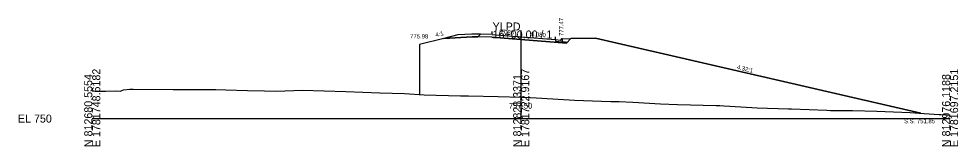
# Model space of a CAD drawing. Extents: x -26 to 353, y -10 to 9080.
# Drawn here: x -25.7 to 302.8, y 5990.3 to 6035 of the extents above; entities that cross this region are included whole.
import ezdxf

# ---------------------------------------------------------------- set-up
doc = ezdxf.new("R2010")
doc.units = 0
for name, color, linetype in [('Exist Cross Section Cell', 7, 'Continuous'), ('Exist XS Center Line Elevation Label', 7, 'Continuous'), ('Exist XS Ground Line', 7, 'Continuous'), ('Prop XS Ditch Slope Text', 7, 'Continuous'), ('Prop XS Dump Level', 7, 'Continuous'), ('Prop XS Earthwork Shape', 7, 'Continuous'), ('Prop XS EOT Tick Mark', 7, 'Continuous'), ('Prop XS Finish Grade', 7, 'Continuous'), ('Prop XS Finish Grade CurbGutter', 7, 'Continuous'), ('Prop XS Finish Grade Earthwork', 7, 'Continuous'), ('Prop XS Finish Grade Paved Shoulder', 7, 'Continuous'), ('Prop XS Finish Grade Pavement', 7, 'Continuous'), ('Prop XS Hydro Elevations', 7, 'Continuous'), ('Prop XS Pvmt Edge Slope', 7, 'Continuous'), ('Prop XS SE Text', 7, 'Continuous'), ('Prop XS Side Slope Text', 7, 'Continuous'), ('Prop XS SS Elevation Text', 7, 'Continuous'), ('Prop XS Subgrade CurbGutter', 7, 'Continuous'), ('Prop XS Subgrade Earthwork', 7, 'Continuous'), ('Scratch_Level_3', 7, 'Continuous')]:
    doc.layers.add(name, color=color, linetype=linetype)

msp = doc.modelspace()

# ---------------------------------------------------------------- linework, layer by layer
at = {"layer": 'Exist Cross Section Cell'}
for p, q in [((150, 6000), (150, 6030.89)), ((0, 6000), (150, 6000)), ((150, 6000), (300, 6000))]:
    msp.add_line(p, q, dxfattribs=at)
at = {"layer": 'Exist XS Ground Line'}
for p, q in [((0, 6009.7), (1.2, 6009.63)), ((1.2, 6009.63), (2.88, 6009.62)), ((2.88, 6009.62), (4.61, 6009.63)), ((4.61, 6009.63), (8.26, 6009.69)), ((8.26, 6009.69), (9.86, 6009.64)), ((9.86, 6009.64), (10.37, 6009.88)), ((10.37, 6009.88), (10.95, 6010.14)), ((10.95, 6010.14), (13.17, 6010.27)), ((13.17, 6010.27), (14.25, 6010.3)), ((14.25, 6010.3), (28.29, 6010.15)), ((28.29, 6010.15), (32.05, 6010.15)), ((32.05, 6010.15), (43.24, 6010.15)), ((43.24, 6010.15), (46.75, 6010.13)), ((46.75, 6010.13), (54.28, 6009.89)), ((54.28, 6009.89), (60.18, 6009.68)), ((60.18, 6009.68), (64.33, 6009.62)), ((64.33, 6009.62), (73.47, 6009.91)), ((73.47, 6009.91), (88.65, 6009.5)), ((88.65, 6009.5), (100.57, 6009)), ((100.57, 6009), (109.18, 6008.8)), ((109.18, 6008.8), (116.09, 6008.35)), ((116.09, 6008.35), (128.74, 6008.02)), ((128.74, 6008.02), (131.54, 6007.99)), ((131.54, 6007.99), (141.98, 6007.76)), ((141.98, 6007.76), (150, 6007.5)), ((150, 6007.5), (151.19, 6007.46)), ((151.19, 6007.46), (157.21, 6007.18)), ((157.21, 6007.18), (168.61, 6006.46)), ((168.61, 6006.46), (178.07, 6006.11)), ((178.07, 6006.11), (181.38, 6006.04)), ((181.38, 6006.04), (184.25, 6005.98)), ((184.25, 6005.98), (189.04, 6005.79)), ((189.04, 6005.79), (198.71, 6005.18)), ((198.71, 6005.18), (204.66, 6004.9)), ((204.66, 6004.9), (218.25, 6004.6)), ((218.25, 6004.6), (219.46, 6004.55)), ((219.46, 6004.55), (220.83, 6004.47)), ((220.83, 6004.47), (222.96, 6004.37)), ((222.96, 6004.37), (232.53, 6003.82)), ((232.53, 6003.82), (243.45, 6003.38)), ((243.45, 6003.38), (244.48, 6003.38)), ((244.48, 6003.38), (256.91, 6002.94)), ((256.91, 6002.94), (258.13, 6002.84)), ((258.13, 6002.84), (265.91, 6002.84)), ((265.91, 6002.84), (274.38, 6002.65)), ((274.38, 6002.65), (286.05, 6002.1)), ((286.05, 6002.1), (289.16, 6001.89)), ((289.16, 6001.89), (296.17, 6001.46)), ((296.17, 6001.46), (296.82, 6001.45)), ((296.82, 6001.45), (300, 6001.26))]:
    msp.add_line(p, q, dxfattribs=at)
at = {"layer": 'Prop XS Dump Level'}
for p, q in [((139.8, 6029.48), (150, 6028.67)), ((150, 6028.67), (162, 6027.71))]:
    msp.add_line(p, q, dxfattribs=at)
at = {"layer": 'Prop XS Earthwork Shape'}
msp.add_lwpolyline([(258.13, 6002.84), (265.91, 6002.84), (274.38, 6002.65), (286.05, 6002.1), (289.16, 6001.89), (289.8, 6001.85), (176, 6028.21), (167.39, 6028.03), (165.84, 6026.48), (149.93, 6027.75), (139.75, 6028.57), (134.9, 6028.66), (132.82, 6028.7), (122.97, 6028.11), (114.43, 6025.98), (114.43, 6008.46), (116.09, 6008.35), (128.74, 6008.02), (131.54, 6007.99), (141.98, 6007.76), (150, 6007.5), (151.19, 6007.46), (157.21, 6007.18), (168.61, 6006.46), (178.07, 6006.11), (181.38, 6006.04), (184.25, 6005.98), (189.04, 6005.79), (198.71, 6005.18), (204.66, 6004.9), (218.25, 6004.6), (219.46, 6004.55), (220.83, 6004.47), (222.96, 6004.37), (232.53, 6003.82), (243.45, 6003.38), (244.48, 6003.38), (256.91, 6002.94)], close=True, dxfattribs=at)
at = {"layer": 'Prop XS EOT Tick Mark'}
for p, q in [((139.8, 6029.48), (139.8, 6030.48)), ((162, 6027.71), (162, 6028.71))]:
    msp.add_line(p, q, dxfattribs=at)
at = {"layer": 'Prop XS Finish Grade'}
for p, q in [((127.8, 6029.32), (122.97, 6028.11)), ((132.8, 6029.62), (127.8, 6029.32)), ((135.8, 6029.56), (132.8, 6029.62)), ((164.5, 6027.97), (167.39, 6028.03))]:
    msp.add_line(p, q, dxfattribs=at)
at = {"layer": 'Prop XS Finish Grade CurbGutter'}
for p, q in [((162, 6027.71), (163.75, 6027.5)), ((163.75, 6027.5), (163.87, 6027.52)), ((163.87, 6027.52), (163.97, 6027.61)), ((163.97, 6027.61), (164.03, 6027.86)), ((164.03, 6027.86), (164.12, 6027.95)), ((164.25, 6027.97), (164.12, 6027.95)), ((164.5, 6027.97), (164.25, 6027.97))]:
    msp.add_line(p, q, dxfattribs=at)
at = {"layer": 'Prop XS Finish Grade Earthwork'}
for p, q in [((122.97, 6028.11), (114.43, 6025.98)), ((114.43, 6025.98), (114.43, 6008.46)), ((167.39, 6028.03), (176, 6028.21)), ((176, 6028.21), (289.8, 6001.85))]:
    msp.add_line(p, q, dxfattribs=at)
at = {"layer": 'Prop XS Finish Grade Paved Shoulder'}
msp.add_line((139.8, 6029.48), (135.8, 6029.56), dxfattribs=at)
at = {"layer": 'Prop XS Finish Grade Pavement'}
for p, q in [((139.8, 6029.48), (150, 6028.67)), ((150, 6028.67), (162, 6027.71))]:
    msp.add_line(p, q, dxfattribs=at)
at = {"layer": 'Prop XS Pvmt Edge Slope'}
for p, q in [((135.8, 6029.56), (134.9, 6028.66)), ((164.5, 6026.93), (165.5, 6026.85)), ((165.5, 6026.85), (165.84, 6026.48))]:
    msp.add_line(p, q, dxfattribs=at)
at = {"layer": 'Prop XS Subgrade CurbGutter'}
for p, q in [((162, 6027.71), (162, 6027.13)), ((162, 6027.13), (164.5, 6026.93)), ((164.5, 6026.93), (164.5, 6027.97))]:
    msp.add_line(p, q, dxfattribs=at)
at = {"layer": 'Prop XS Subgrade Earthwork'}
for p, q in [((132.82, 6028.7), (122.97, 6028.11)), ((134.9, 6028.66), (132.82, 6028.7)), ((139.75, 6028.57), (134.9, 6028.66)), ((139.75, 6028.57), (149.93, 6027.75)), ((149.93, 6027.75), (165.84, 6026.48)), ((165.84, 6026.48), (167.39, 6028.03))]:
    msp.add_line(p, q, dxfattribs=at)
at = {"layer": 'Scratch_Level_3'}
for p, q in [((127.8, 6029.32), (122.97, 6028.11)), ((122.97, 6028.11), (132.82, 6028.7)), ((132.8, 6029.62), (127.8, 6029.32)), ((135.8, 6029.56), (132.8, 6029.62)), ((132.82, 6028.7), (134.9, 6028.66)), ((134.9, 6028.66), (135.8, 6029.56))]:
    msp.add_line(p, q, dxfattribs=at)

# ---------------------------------------------------------------- texts
at = {"layer": 'Exist Cross Section Cell'}
for s, p in [('YLPD', (140, 6030.89)), ('16+00.00 / 1', (140, 6028.09)), ('EL 750', (-26, 5998.6))]:
    msp.add_text(s, height=2.8, dxfattribs=at).set_placement(p)
for s, p in [('N 812680.5554', (0, 5990)), ('E 1781748.6182', (2.8, 5990)), ('E 1781722.9167', (152.8, 5990)), ('N 812976.1188', (300, 5990)), ('E 1781697.2151', (302.8, 5990)), ('N 812828.3371', (150, 5990))]:
    msp.add_text(s, height=2.8, rotation=90, dxfattribs=at).set_placement(p)
at = {"layer": 'Exist XS Center Line Elevation Label'}
msp.add_text('757.50', height=2, dxfattribs=at).set_placement((145.71, 6003.5))
at = {"layer": 'Prop XS Ditch Slope Text'}
msp.add_text('775.98', height=1.5, dxfattribs=at).set_placement((111.17, 6028.09))
at = {"layer": 'Prop XS Dump Level'}
msp.add_text('Case4', height=0.04, dxfattribs=at).set_placement((127.8, 6029.28))
at = {"layer": 'Prop XS Hydro Elevations'}
msp.add_text('777.47', height=1.5, rotation=90, dxfattribs=at).set_placement((164.75, 6028.97))
at = {"layer": 'Prop XS SE Text'}
for p in [(142.28, 6029.78), (153.38, 6028.9)]:
    msp.add_text('0.080', height=1.5, rotation=355.4261, dxfattribs=at).set_placement(p)
at = {"layer": 'Prop XS Side Slope Text'}
for s, rotation, p in [('4:1', 14.0362, (120.2, 6028.57)), ('4.32:1', 345.9638, (225.33, 6017.42))]:
    msp.add_text(s, height=1.5, rotation=rotation, dxfattribs=at).set_placement(p)
at = {"layer": 'Prop XS SS Elevation Text'}
msp.add_text('S.S. 751.85', height=1.5, dxfattribs=at).set_placement((283.91, 5998.37))

doc.saveas('drawing.dxf')
